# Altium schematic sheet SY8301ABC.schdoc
size 127 x 101 mm
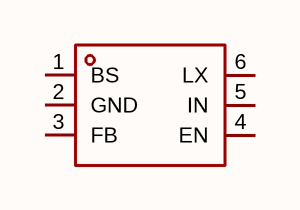
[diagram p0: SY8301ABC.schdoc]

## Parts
U?  sy8301abc  [SOT-23-6_L2.9-W1.6-P0.95-LS2.8-BL]  (value not drawn)

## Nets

Not connected (* = marked no-connect by the designer): U? 1(BS) 2(GND) 3(FB) 4(EN) 5(IN) 6(LX)

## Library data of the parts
U? = sy8301abc: 功能类型:降压型;工作电压:4.5V~40V;输出电压:-;输出电流:1A;输出类型:可调;; Manufacturer: Silergy(矽力杰); AddInBom: yes; ModelId: 18da8f6c14a34920b3e136b5c401a119; ModelName: SOT-23-6_L2.9-W1.6-H1.5-LS2.8-P0.95; ModelTransform: 110.236,113.364,0,90,0,0,0.0005,0.0005,0; Function: 降压型; Output Current: 1A; Frequency - Switching: 1.6MHz~2.4MHz; Synchronous Rectifier: 是; Number of Outputs: 1; Topology: 降压式; Quiescent Current: 22uA; Switch tube (built-in/external): 内置; Output Type: 可调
